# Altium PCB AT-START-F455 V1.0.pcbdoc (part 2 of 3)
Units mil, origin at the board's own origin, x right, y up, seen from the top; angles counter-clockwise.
Board outline 10945.53 x 3554 mil, 2 copper layers (Top Layer, Bottom Layer); 149 components, 197 nets, 740 pads, 768 vias.
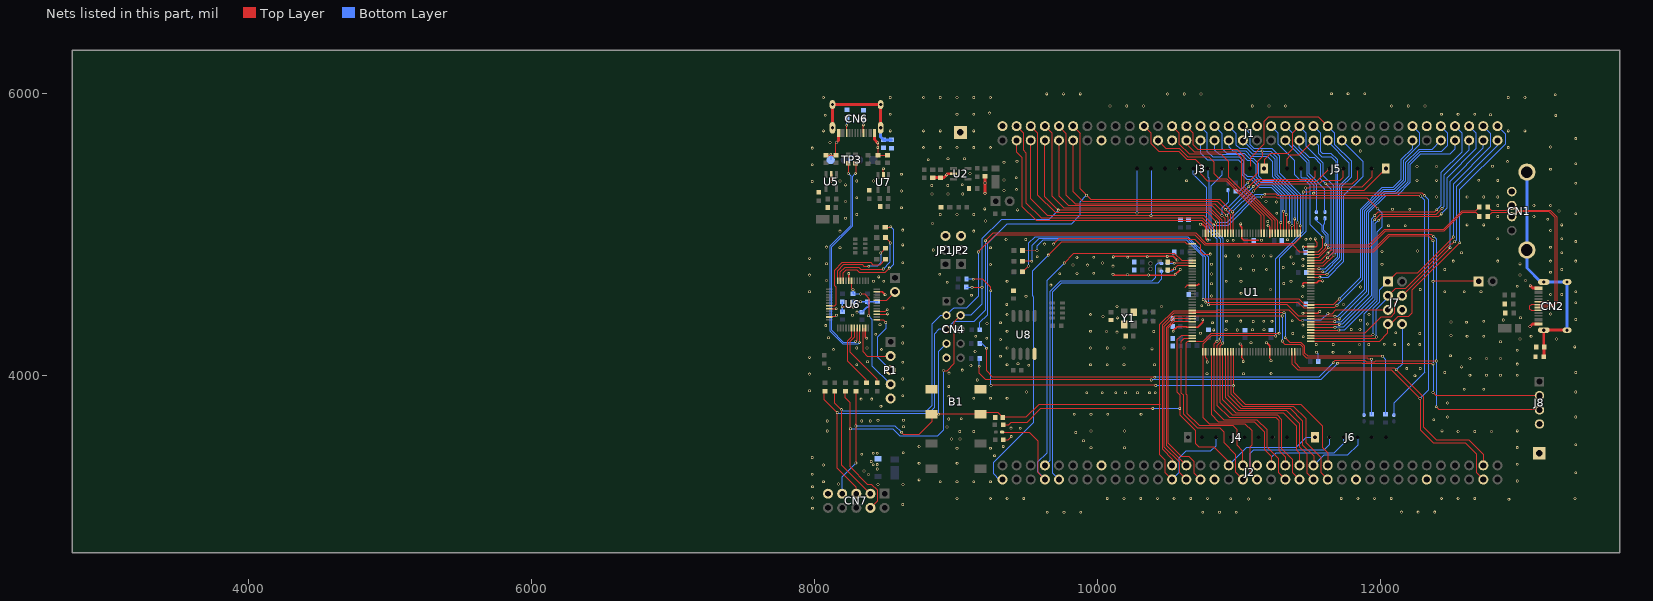
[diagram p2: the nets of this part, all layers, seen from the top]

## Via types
v1: diameter 19.7, hole 11.8, Top Layer to Bottom Layer, 425 vias
v2: diameter 19.68, hole 11.81, Top Layer to Bottom Layer, 331 vias
v3: diameter 31.5, hole 19.68, Top Layer to Bottom Layer, 10 vias
v4: diameter 27.56, hole 19.68, Top Layer to Bottom Layer, 2 vias

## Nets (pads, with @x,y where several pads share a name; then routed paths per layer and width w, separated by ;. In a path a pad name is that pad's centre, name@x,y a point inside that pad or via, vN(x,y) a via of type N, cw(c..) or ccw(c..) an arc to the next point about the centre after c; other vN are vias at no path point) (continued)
BOOT0: CN4.4 CN7.4 J1.66 R13.2 R45.2 U1.138 | length 5703.8
  Top Layer w6: R45.2@8218.66,3892.68 8218.66,3846.33 8253.97,3811.01 8253.97,3355.87 8378.26,3231.58 8403.96,3231.58 8446.06,3189.58 8446.06,3117.18 CN7.4@8395.46,3066.58 ; v2(8912.21,4037.97) 8937.81,4037.97 8987.5,4087.66 8987.5,4382.24 CN4.4@9033.23,4427.98 ; v2(9113.66,4626.6) v2(9184.53,4626.6) ; J1.66@9629.16,5665.18 9629.16,5266.98 v2(9724.26,5171.98) 10791.16,5171.98 10863.86,5099.28 U1.138@10863.86,5008.28
  Bottom Layer w6: v2(8254.21,3625.97) 8554.21,3625.97 8603.22,3576.97 8870.92,3576.97 8912.21,3618.25 v2(8912.21,4037.97) ; CN4.4@9033.26,4427.98 9105.76,4428.18 9183.26,4505.68 9183.26,4968.98 9319.14,5104.86 9657.14,5104.86 v2(9724.26,5171.98) ; R13.2@9071.76,4627.98 9073.06,4626.58 v2(9113.66,4626.6)
CC1: CN6.A5 R86.1 | length 101.4
  Top Layer w6: v1(8345.57,5774.61) 8346.41,5773.78 CN6.A5@8346.41,5717.9
  Bottom Layer w6: v1(8345.57,5774.61) R86.1@8345.57,5818.95
CC2: CN6.B5 R87.1 | length 106.2
  Top Layer w6: v1(8227.57,5772.61) 8228.31,5771.88 CN6.B5@8228.31,5717.9
  Bottom Layer w6: v1(8227.57,5772.61) 8227.57,5799.08 8229.57,5801.08 R87.1@8229.57,5822.95
EGND: C20.2 CN6.13 CN6.14 CN6.15 CN6.16 R88.1 | length 818.4
  Top Layer w20: CN6.14@8127.11,5753.9 CN6.16@8127.11,5918.5 CN6.15@8467.31,5918.5 CN6.13@8467.31,5753.9
  Bottom Layer w20: CN6.13@8467.31,5753.9 8467.31,5690.44 C20.2@8489.57,5668.17 8543.47,5668.17 R88.1@8543.57,5668.27
EGND1: C21.1 CN1.SH1 CN1.SH2 CN2.13 CN2.14 CN2.15 CN2.16 R35.2 | length 1697.7
  Top Layer w6: R35.2@13157.7,4135.42 R35.2@13159.6,4137.32
  Top Layer w20: C21.1@13156.94,4203.42 CN2.13@13156.94,4323.72 CN2.15@13321.54,4323.72 ; R35.2@13159.6,4137.32 C21.1@13159.6,4203.42
  Bottom Layer w20: CN1.SH1@13037.41,5440.9 CN1.SH2@13037.41,4889.71 13037.41,4761.79 13135.29,4663.92 CN2.14@13156.94,4663.92 CN2.16@13321.54,4663.92 CN2.15@13321.54,4323.72
GND: B1.2 B1.4 C1.1 C2.1 C3.1 C4.1 C5.2 C6.2 C7.2 C8.1 C9.1 C10.1 C11.1 C12.1 C13.2 C14.1 C15.1 C16.1 C17.1 C18.1 C19.1 C20.1 C21.2 C22.1 C23.2 C24.2 C25.2 C26.2 C27.2 C28.2 C29.2 C30.2 C31.2 C32.2 C33.2 C34.2 C35.2 C36.2 C37.2 C38.2 C39.2 C40.2 CN1.4 CN2.A1B12 CN2.B1A12 CN4.9 CN6.A1B12 CN6.B1A12 CN7.9 D4.2 J1.11 J1.22 J1.35 J1.48 J1.58 J1.71 J2.16 J2.31 J2.38 J2.51 J2.61 J3.7 J4.6 J4.7 J7.6 J8.4 JP1.3 JP2.3 LED1.2 P1.5 R15.2 R18.1 R32.1 R33.1 R35.1 R49.2 R51.2 R86.2 R87.2 R88.2 T1.1 T2.1 TP3.4 U1.16 U1.31 U1.38 U1.51 U1.61 U1.83 U1.94 U1.107 U1.120 U1.130 U1.143 U2.2 U5.2 U6.8 U6.20 U6.23 U6.35 U6.39 U6.40 U6.47 U7.2 U8.4 Y1.2 Y1.4 | length 5994.8
  Top Layer w5.98: v1(9689.57,4931.61) 9729.57,4971.61 10638.94,4971.61 10643.09,4967.46
  Top Layer w6: C18.1@8080.37,5561.37 8149.57,5561.37 C19.1@8150.37,5560.57 8150.37,5644.21 v2(8156.11,5649.96) ; U6.23@8104.58,4416.72 8142.48,4416.72 v2(8155.17,4429.41) ; U6.20@8104.58,4475.78 8153.2,4475.78 v2(8153.97,4475.01) ; v2(8196.37,4489.41) 8197.17,4488.61 8272.57,4488.61 v2(8273.57,4487.61) ; U6.39@8439.23,4436.41 8515.15,4436.41 v2(8516.94,4438.2) ; U6.40@8439.23,4456.09 8501.93,4456.09 v2(8514.03,4468.19) ; v2(8447.17,5647.41) v1(8447.17,5615.61) 8447.17,5584.75 8448.56,5583.36 C15.1@8448.56,5561.61 C16.1@8517.56,5561.61 ; v2(8487.17,5464.21) 8487.34,5464.05 U7.2@8487.34,5418.39 ; R18.1@9335.87,3547.97 9369.42,3547.97 v1(9391.96,3570.51) ; 10618.26,4623.08 10634.36,4639.18 ; 10643.09,4967.46 10689.19,4967.46 10729.37,4927.27 10729.37,4880.81 10749.38,4860.8 v1(10798.05,4860.8) ; U1.38@10765.46,4171.68 10765.46,4128.38 10776.57,4117.27 v1(10776.57,4097.61) ; U1.51@11021.36,4171.68 11021.36,4127.78 11031.5,4117.74 ; v1(11031.57,4102.61) 11031.57,4117.67 ; 11218.16,4134.08 11218.16,4127.28 11227.57,4117.87 v1(11227.57,4106.61) ; v1(11453.48,4442.3) U1.83@11508.48,4442.35 ; v1(11541.13,4968.64) 11541.13,4954.35 11551.32,4944.15 11551.32,4916.85 11549.26,4914.78
  Top Layer w10: U6.8@8242.36,4672.68 8242.43,4672.75 v2(8242.43,4723.22) ; U6.35@8360.49,4337.98 8360.49,4275.35 v2(8369.66,4266.18) ; U6.47@8439.26,4593.88 8478.39,4594.19 v2(8499.17,4573.41) ; v1(10110.79,4718.95) 10118.65,4711.1 10544.67,4711.1 v1(10585.67,4752.1) ; v1(10111.81,4841.3) 10115.31,4844.81 v1(10495.01,4844.81) 10538.1,4844.81 v1(10563.99,4818.91) ; v1@10538.26,4321.28 10565.16,4348.18 10628.39,4348.18 10632.7,4343.88 U1.31@10671.86,4343.93 10711.26,4343.88 10744.91,4377.54 v1(10744.91,4396.83) ; 10631.46,4639.18 10634.36,4639.18 U1.16@10671.86,4639.2 10708.16,4639.18 10721.56,4652.58 ; v1(10729.21,5072.19) 10743.36,5072.19 10765.36,5050.18 U1.143@10765.37,5008.31 10765.36,4968.98 v1@10772.76,4961.68 ; v1(11009.57,4225.61) 11021.26,4213.93 U1.51@11021.27,4171.68 11021.26,4129.48 ; v1@11011.86,5076.32 11011.86,5061.58 11021.36,5052.18 11021.36,5008.31 11021.36,4972.08 11034.26,4959.18 11143.06,4959.18 ; v1(11196.57,4233.61) 11218.16,4212.03 11218.16,4171.68 11218.16,4134.08 ; v1@11214.76,5056.08 11218.16,5052.78 11218.16,5008.31 11218.16,4975.38 ; v1(11453.53,4634.21) 11453.19,4634.55 11453.19,4651.81 11460.26,4658.88 U1.94@11508.48,4658.89 11553.16,4658.88 11565.89,4671.61 v2(11592.57,4671.61) ; v1(11456.57,4910.61) 11456.57,4914.78 U1.107@11508.48,4914.79 11549.26,4914.78 ; U1.83@11508.56,4442.28 11559.66,4442.28 v1(11572.76,4455.38)
  Top Layer w15: U5.2@8118.56,5424.05 8119.17,5423.44 v2(8119.17,5375.81)
  Top Layer w20: v2(8156.11,5649.96) 8170.41,5664.25 CN6.B1A12@8170.41,5717.9 ; CN6.A1B12@8424.21,5717.9 8424.21,5670.38 v2(8447.17,5647.41) ; C5.2@8836.21,5402.05 C6.2@8891.21,5402.05 8915.36,5402.08 v1(8934.33,5421.12) 8942.16,5428.98 U2.2@8984.26,5428.98 ; C7.2@9206.16,5410.48 v1(9206.16,5364.21) v1(9206.16,5291.98) v1@9206.26,5291.98 ; v1(13059.04,4349.42) 13076.44,4366.82 CN2.A1B12@13120.94,4366.82 ; v1(13061.04,4637.42) 13077.84,4620.62 CN2.B1A12@13120.94,4620.62
  Bottom Layer w5.98: v1(11549.18,4167.71) 11561.77,4155.12 C29.2@11561.77,4101.97
  Bottom Layer w6: TP3.4@8114.58,5526.61 v1(8114.57,5566.61) ; v2(8273.57,4487.61) 8273.97,4488.01 C22.1@8273.97,4524.65 ; v2(8300.41,4450.97) C11.1@8335.17,4450.97 ; v1(10781.23,4959.9) 10802.13,4959.9 10802.77,4959.26 ; v1(11456.57,4910.61) 11456.57,4889.17 C32.2@11473.13,4872.61
  Bottom Layer w10: C12.1@8196.37,4524.65 v2(8196.37,4489.41) 8196.77,4489.01 C10.1@8196.77,4453.77 ; C22.1@8273.97,4524.65 v2(8325.27,4524.65) C9.1@8376.37,4524.65 ; C11.1@8335.17,4450.97 8371.21,4487.01 8375.17,4487.01 8382.24,4494.09 8382.24,4504.09 8376.37,4509.96 C9.1@8376.37,4524.65 ; C9.1@8376.37,4525.05 C9.1@8376.37,4524.65 ; C8.1@8446.37,4525.85 8418.65,4525.85 8417.45,4524.65 C9.1@8376.37,4524.65
  other v1: 9646.44,3035.82 9764.55,3035.82 9882.66,3035.82 10745.74,3035.82 10863.85,3035.82 10981.96,3035.82 12150.21,3036.6 12268.32,3036.6 12386.43,3036.6 7986.57,3063.61 8624.57,3090.61 12910.14,3128.29 11068.29,3129.68 10942.92,3130.71 11218.56,3130.71 9007.66,3133.82 9243.88,3133.82 9361.99,3133.82 9480.1,3133.82 10070.65,3133.82 10188.76,3133.82 10306.87,3133.82 10424.98,3133.82 10543.09,3133.82 10661.2,3133.82 10779.31,3133.82 11724.2,3133.82 11842.31,3133.82 11960.42,3133.82 12078.53,3133.82 12432.86,3133.82 12550.97,3133.82 12669.08,3133.82 13377.74,3133.82 7986.57,3136.61 7986.57,3216.61 8449.57,3231.61 8625.57,3231.61 8169.57,3235.61 8062.78,3251.94 8889.55,3251.94 9007.66,3251.94 9125.77,3251.94 9243.88,3251.94 8739.57,3264.39 8382.07,3302.11 7984.57,3304.39 8350.57,3327.61 8443.57,3341.61 8062.78,3370.05 8415.07,3372.14 8443.57,3372.61 9008.57,3381.61 8739.57,3382.5 8402,3394.41 7984.57,3422.5 9273.57,3434.61 8333.57,3445.61 8415.57,3452.61 8443.57,3452.61 8627.57,3456.61 9007.66,3488.16 9243.88,3488.16 9955.57,3491.61 10191.55,3492.51 8739.57,3500.61 9334.55,3501.51 9902.57,3541.61 8968.57,3553.61 9028.57,3553.61 9847.57,3599.61 9027.66,3606.27 9125.77,3606.27 12550.97,3606.27 12669.08,3606.27 12787.19,3606.27 8089.57,3610.61 9955.33,3610.62 10191.55,3610.62 9455.57,3629.61 9389.57,3630.61 8936.59,3638.67 8629.57,3640.61 8089.57,3680.61 8334.57,3680.61 8394.57,3680.61 8449.57,3685.61 8629.57,3685.61 8949.57,3695.61 9037.57,3696.61 9837.22,3728.73 9955.33,3728.73 10073.44,3728.73 10309.66,3728.73 8469.57,3785.61 8329.57,3835.61 8404.57,3835.61 9125.77,3842.49 9243.88,3842.49 9361.99,3842.49 8949.57,3855.61 8624.57,3859.39 9924.57,3880.61 10034.57,3880.61 10129.57,3880.61 10199.57,3880.61 10284.57,3880.61 10369.57,3880.61 10409.57,3880.61 9499.57,3885.61 7964.57,3894.39 8949.57,3925.61 9150.77,3970.6 8624.57,3977.5 7964.57,4012.5 10775.57,4015.31 11033.65,4015.54 11228.8,4015.85 8951.08,4019.38 9044.57,4040.61 12187.22,4051.45 8104.57,4052.5 9105.77,4073.71 9514.57,4075.61 8299,4078.71 9361.99,4078.71 9952.54,4078.71 10070.65,4078.71 10188.76,4078.71 10404.57,4079.39 9439.57,4085.61 8624.57,4095.61 8374.57,4100.61 7964.57,4130.61 9314.57,4139.39 11667.29,4167.71 11785.4,4167.71 9135.77,4171.82 8134.57,4185.61 8474.57,4185.61 10386.94,4190.74 8299,4196.82 8371.4,4197.15 9361.99,4196.82 9952.54,4196.82 10070.65,4196.82 10188.76,4196.82 13376.17,4204.95 11547.64,4221.77 11668.11,4222.05 11853.37,4222.42 11919.21,4221.67 12029.3,4223.51 8624.57,4232.5 11086.46,4234.02 9314.57,4257.5 13247.06,4261 9218.34,4266.61 8099.57,4269.39 11456.18,4277.39 9139.57,4280.61 12500.3,4285.22 8432.74,4294.95 11381.5,4299.17 10730.04,4301.05 12110.21,4304.89 10139.64,4309.43 10064.81,4313.39 10399.24,4313.56 9361.99,4314.93 9952.54,4314.93 10536.27,4315.64 10988.84,4324.34 10823.72,4325.3 11178.64,4325.5 10909.7,4325.83 11096.88,4325.83 11796.21,4328.23 11856.41,4327.54 8624.57,4350.61 8079.57,4355.61 11453.44,4358.89 8463.33,4361.23 11911.3,4366.97 9219.57,4370.61 9314.57,4375.61 10813.35,4375.83 12609.62,4379.62 12500.6,4380.55 11102.16,4385 10914.13,4386.53 11013.73,4387.03 11176.75,4386.64 11234.34,4386.64 11378.97,4389.82 11860.56,4393.27 10141.94,4409.99 10040.24,4419.68 8269,4428.04 9361.99,4433.04 9952.54,4433.04 11921.44,4433.4 8625.22,4479.93 10454.31,4490.33 10138.63,4491.28 10738.1,4495.53 11740.53,4504.27 9359.57,4505.61 11451.68,4561.79 9495.17,4563.45 10808.14,4564.69 9109.57,4570.61 11016.87,4583.72 7964.57,4594.39 11224.09,4610.88 11861.61,4628.12 9671.57,4641.61 10807.75,4650.9 11318.07,4653.66 8938.27,4661.7 8417.11,4669.26 9361.99,4669.26 10910.91,4669.26 11015.53,4669.26 11369.87,4669.26 8489.51,4669.59 8084.57,4674.39 8454.25,4700 7964.57,4712.5 10361.2,4713.59 10212.96,4717.08 10551.25,4717.89 8886.25,4718.87 10807.6,4720.14 9734.57,4722.61 9855.76,4724.84 9973.91,4725.6 11104.74,4746.83 11197.11,4751.82 11013.41,4757.21 11315.3,4766.21 10110.53,4776.01 11453.53,4779.43 9930.71,4783.37 9827.67,4784.29 9243.88,4787.37 10807.5,4788.89 12012.44,4789.56 8084.57,4792.5 11387.57,4795.61 10036.4,4797.96 8624.57,4799.39 11453.53,4824.94 7964.57,4830.61 9855.25,4837.91 9974.68,4839.18 11370.06,4841.01 10352.6,4841.64 9575.57,4842.61 11000.57,4847.61 11097.57,4847.61 11174.57,4847.61 10907.57,4848.61 11227.57,4848.61 12012.54,4880.38 12263.98,4882.46 8839.57,4890.61 8180.89,4905.48 9243.88,4905.48 8084.57,4910.61 8624.57,4926.25 9626.57,4931.61 10919.94,4958 10961.57,4958.61 11160.57,4959.61 11345.57,4962.61 9355.15,4964.33 9493.64,4964.29 11474.74,4966.62 11507.95,4967.22 8180.89,5023.59 9125.77,5023.59 8624.26,5030.62 12059.64,5060.92 12178.03,5061.23 11207.57,5062.61 11013.57,5074.61 8834.96,5078.07 11205.57,5091.61 9209.57,5095.61 8219.57,5114.39 8299,5141.7 8889.55,5141.7 9007.66,5141.7 9125.77,5141.7 9435.18,5173.68 12087.17,5178.39 12209.79,5177.93 9204.57,5180.61 8614.57,5189.39 8219.57,5232.5 8299,5259.81 8831.46,5285.61 8944.57,5285.61 9047.68,5285.61 8614.57,5307.5 9339.57,5310.61 9428.04,5317.21 8829.57,5345.61 8942.68,5345.61 8219.57,5350.61 9045.17,5351.15 7984.57,5374.39 8180.89,5377.92 8299,5377.92 8417.11,5377.92 10631.33,5379.73 12696.74,5383.89 9339.57,5384.93 9427.35,5400.89 8614.57,5425.61 9099.57,5430.61 12793.91,5482.06 7984.57,5492.5 9339.57,5510.61 12900.76,5515.24 9431.5,5517.07 8804.71,5527.77 9060.59,5535.15 8944.57,5535.61 11859.02,5590.1 7984.57,5610.61 8771.44,5614.14 8889.55,5614.14 9007.66,5614.14 9125.77,5614.14 9243.88,5614.14 12905.3,5614.14 8109.57,5650.61 8062.78,5732.25 8535.22,5732.25 8771.44,5732.25 8889.55,5732.25 9125.77,5732.25 12905.3,5732.25 13023.41,5732.25 13240.91,5841.93 8076.21,5843.18 12780.53,5846.89 8535.22,5850.36 9007.66,5850.36 9125.77,5850.36 12432.86,5850.36 12550.97,5850.36 12669.08,5850.36 9237.66,5857.97 11095.21,5908.35 11213.32,5908.35 11331.43,5908.35 12080.8,5908.48 12198.91,5908.48 12317.02,5908.48 10089.92,5908.57 10208.03,5908.57 10326.14,5908.57 8062.78,5968.47 8535.22,5968.47 8771.44,5968.47 8889.55,5968.47 9007.66,5968.47 9125.77,5968.47 9243.88,5968.47 12905.3,5968.47 13023.41,5968.47 13237.8,5987.23 10497.05,5992.74 10615.16,5992.74 10733.27,5992.74 9642.7,5994.01 9760.81,5994.01 9878.92,5994.01 11655.09,5994.49 11773.2,5994.49 11891.31,5994.49
  other v2: 12968.94,3256.52 13382.33,3315.58 12968.94,3374.63 12968.94,3492.74 13382.33,3512.43 12437.44,3610.85 12968.94,3610.85 12378.39,3689.59 12476.81,3709.28 13382.33,3709.28 12476.81,3807.7 13382.33,3886.44 12594.92,3906.13 12732.72,3906.13 12245.65,4001.58 12634.29,4004.55 12752.4,4004.55 12850.83,4004.55 12968.94,4004.55 12457.13,4024.24 13382.33,4024.24 12283.52,4052.08 12575.24,4063.61 12968.94,4083.29 12634.29,4122.66 12752.4,4122.66 12850.83,4122.66 12496.5,4142.35 12968.94,4181.72 12102.8,4221.09 12201.22,4221.09 12279.96,4221.09 12850.83,4240.77 12988.62,4260.46 12614.61,4280.14 12732.72,4280.14 13067.36,4280.14 12279.96,4299.83 12733.17,4386.53 12870.02,4395.19 13382.33,4398.25 12992.44,4411.43 13205.16,4437.62 13264.22,4476.99 13382.33,4516.36 13205.16,4575.42 13283.9,4575.42 12457.13,4595.1 12594.92,4595.1 12713.03,4595.1 13382.33,4595.1 12283.31,4610.65 12968.94,4634.47 13027.99,4673.84 12988.62,4713.21 13205.16,4732.9 12457.13,4752.58 13283.9,4752.58 12988.62,4791.95 12516.18,4811.64 12831.14,4811.64 13205.16,4811.64 13382.33,4811.64 10214.62,4838.9 12575.24,4870.69 13283.9,4870.69 13205.16,4910.06 13382.33,4949.43 12831.14,4969.12 13283.9,4969.12 13205.16,5028.17 12614.61,5067.54 12732.72,5067.54 13283.9,5067.54 13185.48,5106.91 12831.14,5126.6 13087.05,5126.6 13382.33,5146.28 11269.02,5149.4 13264.22,5165.97 12831.14,5205.34 13087.05,5205.34 13205.16,5205.34 11267.52,5229.07 11192.66,5232.67 12398.07,5264.39 12614.61,5264.39 12732.72,5264.39 12831.14,5264.39 13382.33,5362.82 12260.28,5382.5 12398.07,5382.5 12831.14,5382.5 13205.16,5461.24 12260.28,5480.93 12398.07,5480.93 13382.33,5500.61 13205.16,5618.73 13382.33,5677.78
LD1: LD1.2 U6.10 | length 760.9
  Top Layer w6: U6.10@8203.01,4672.63 8203.01,4728.05 8223.97,4749.01 8299.93,4749.01 8315.93,4733.01 8499.57,4733.01 v2(8528.37,4761.81) ; LD1.2@8500.43,5052.63 8537.59,5052.63 v2(8538.77,5053.81)
  Bottom Layer w6: v2(8528.37,4761.81) 8530.37,4761.81 8558.77,4790.21 8558.77,5033.81 v2(8538.77,5053.81)
LD2: LD2.2 U6.11 | length 643.9
  Top Layer w6: U6.11@8183.32,4672.63 8183.32,4735.97 8216.77,4769.41 8312.03,4769.41 8326.03,4755.41 v2(8485.57,4755.41) ; LD2.2@8501.39,4978.53 8536.37,4943.56 v2(8536.37,4939.81)
  Bottom Layer w6: v2(8485.57,4755.41) 8536.37,4806.21 v2(8536.37,4939.81)
LD3: LD3.2 U6.12 | length 524.6
  Top Layer w6: U6.12@8163.64,4672.63 8163.64,4744.28 8207.17,4787.81 8337.17,4787.81 8349.13,4775.86 v2(8382.95,4775.86) ; v2(8467.97,4868.61) 8468.42,4868.61 LD3.2@8501.43,4901.63
  Bottom Layer w6: v2(8382.95,4775.86) 8443.61,4775.86 8467.97,4800.21 v2(8467.97,4868.61)
LD4: LD4.2 U6.19 | length 706.4
  Top Layer w6: U6.19@8104.58,4495.46 8143.22,4495.46 8153.17,4505.41 8153.17,4626.61 8141.57,4638.21 8141.57,4748.21 8196.77,4803.41 8397.57,4803.41 8413.57,4787.41 8464.77,4787.41 8501.39,4824.04 LD4.2@8501.39,4825.63
M-ATLK_RX: R48.1 U6.31 | length 483.9
  Top Layer w6: U6.31@8281.76,4337.98 8281.76,4271.98 8249.46,4239.58 8249.46,4170.28 8440.46,3979.28 R48.1@8440.46,3946.58
M-ATLK_TX: R47.1 U6.30 | length 457.3
  Top Layer w6: U6.30@8262.06,4337.98 8262.06,4276.28 8234.66,4248.88 8234.66,4102.88 8366.46,3971.08 R47.1@8366.46,3946.58
M-BOOT0: J9.2 U6.44 | length 154.6
  Top Layer w6: U6.44@8439.26,4534.88 8510.66,4534.88 J9.2@8569.46,4593.68
M-NRST: C22.2 P1.4 U6.7 | length 893.3
  Top Layer w6: U6.7@8262.06,4672.68 8262.06,4619.48 v2(8272.16,4609.38) ; v2(8324.77,4579.01) 8353.97,4579.01 8382.37,4550.61 v2(8382.37,4424.61)
  Bottom Layer w6: C22.2@8273.97,4579.77 8324.01,4579.77 v2(8324.77,4579.01) ; v2(8382.37,4424.61) 8409.57,4397.41 8409.57,4068.77 P1.4@8538.16,3940.18
  Bottom Layer w10: v2(8272.16,4609.38) 8273.97,4607.57 C22.2@8273.97,4579.77
M-SWCLK: P1.3 U6.37 | length 475.2
  Top Layer w6: U6.37@8439.26,4397.04 8484.75,4397.04 v2(8504.37,4377.41)
  Bottom Layer w6: v2(8504.37,4377.41) 8504.37,4333.01 8443.17,4271.81 8443.17,4135.17 P1.3@8538.16,4040.18
M-SWDIO: P1.2 U6.34 | length 376.2
  Top Layer w6: U6.34@8340.8,4337.98 8340.76,4172.56 8373.14,4140.18 P1.2@8538.16,4140.18
M-USB_DM: R12.2 U6.32 | length 1557.9
  Top Layer w6: v2(8289.29,5431.83) 8290.08,5432.61 R12.2@8290.08,5505.16 ; v2(8290.51,4244.08) 8301.46,4255.04 U6.32@8301.46,4337.98
  Bottom Layer w6: v2(8289.29,5431.83) 8270.37,5412.9 8270.37,5061.25 8122.77,4913.65 8122.77,4321.44 8208.23,4235.98 8282.42,4235.98 v2(8290.51,4244.08)
M-USB_DP: R11.2 U6.33 | length 1610.2
  Top Layer w6: R11.2@8238.07,5504.37 8238.07,5432.9 v2(8239.61,5431.36) ; v2(8317.31,4236.99) 8321.16,4240.86 U6.33@8321.16,4337.98
  Bottom Layer w6: v2(8239.61,5431.36) 8258.37,5412.6 8258.37,5066.22 8110.77,4918.62 8110.77,4316.47 8203.26,4223.98 8304.31,4223.98 v2(8317.31,4236.99)
NRST: B1.1 B1.3 C40.1 CN4.7 CN7.7 J2.25 J4.3 J7.5 R46.2 U1.25 | length 7009.8
  Top Layer w6: v2(8292.66,3383.78) 8292.81,3383.93 8292.81,3663.13 8292.66,3662.98 ; v1(8292.66,3645.23) 8292.66,3662.98 ; R46.2@8292.66,3892.68 8292.66,3662.98 ; v2(8616.21,3600.97) 8632.56,3584.61 8738.57,3584.61 8828.03,3674.07 B1.3@8828.03,3728.39 B1.1@9174.49,3728.39 9185.06,3738.98 9298.26,3738.98 C40.1@9331.77,3705.97 9495.26,3705.98 9584.26,3794.98 10439.66,3794.98 10439.66,3796.08 10441.57,3797.96 ; J2.25@10529.17,3267.08 10480.26,3316.08 10480.26,3403.93 10441.57,3442.61 10441.57,3797.96 ; v2(11451.16,4391.98) 11428.2,4391.98 11354.2,4465.98 10846.66,4465.98 10842.76,4461.98 U1.25@10671.86,4462.04 10539.66,4461.98 10441.57,4363.89 10441.57,3797.96 ; v2(11630.21,4440.97) 11659.92,4440.97 11685.51,4466.56 J7.5@12054.81,4466.56
  Bottom Layer w6: CN7.7@8195.43,3166.63 8195.43,3286.55 v2(8292.66,3383.78) ; v1(8292.66,3645.23) 8571.94,3645.23 v2(8616.21,3600.97) ; v2(8879.21,3727.97) 8879.21,4173.95 CN4.7@8933.23,4227.98 ; J2.25@10529.17,3267.08 10579.26,3317.08 10579.26,3420.98 10627.26,3468.98 10803.36,3468.98 10839.86,3505.48 J4.3@10839.86,3565.98 ; v2(11451.16,4391.98) 11581.22,4391.98 v2(11630.21,4440.97)
OTGFS1_D+: CN1.3 CN2.A6 CN2.B6 R30.2 | length 1405.1
  Top Layer w5.98: R30.2@12760.64,5194.62 12785.25,5170.01 12896.06,5170.01 CN1.3@12930.72,5204.67 ; CN2.B6@13120.94,4523.32 13122.01,4523.32 13122.78,4524.08 13184.72,4524.08 v2(13186.21,4525.57)
  Top Layer w6: CN1.3@12930.72,5204.67 12939.2,5204.67 12972.24,5171.63 13200.9,5171.63 13248.97,5123.56 13248.97,4515.74 13216.94,4483.71 v2(13189.49,4483.71) 13121.24,4483.71 CN2.A6@13120.94,4484.02
  Bottom Layer w5.98: v2(13186.21,4525.57) 13189.49,4522.28 v2(13189.49,4483.71)
OTGFS1_D-: CN1.2 CN2.A7 CN2.B7 R31.2 | length 1410.6
  Top Layer w5.98: R31.2@12760.64,5127.69 12760.64,5127.82 12790.87,5158.04 12898.6,5158.04 CN1.2@12930.72,5125.93 ; CN2.B7@13120.94,4464.32 13067.48,4464.32 13055.8,4475.99 13055.8,4492.81 13066.61,4503.62 CN2.A7@13120.94,4503.62
  Top Layer w6: CN1.2@12930.72,5125.93 12939.2,5125.93 12972.9,5159.63 13195.93,5159.63 13236.97,5118.59 13236.97,4520.71 13220.43,4504.17 13121.49,4504.17 CN2.A7@13120.94,4503.62
PA0: J2.34 J6.1 R19.2 U1.34 | length 3215.2
  Top Layer w6: R19.2@9332.66,3653.98 9372.02,3653.98 9391.72,3673.68 9504.96,3673.68 9601.26,3769.98 v2(10391.16,3769.98) ; U1.34@10671.86,4284.87 10592.84,4284.88 10562.26,4254.23 10562.26,3886.38 10583.26,3865.38 10583.26,3769.97 10583.26,3725.98 10692.26,3616.98 10692.26,3523.98 10717.26,3498.98 10823.26,3498.98 10929.16,3392.98 J2.34@10929.17,3367.08
  Bottom Layer w6: v2(10391.16,3769.98) v2(10583.21,3769.97) ; J2.34@10929.17,3367.08 11058.16,3495.98 11406.26,3495.98 11476.26,3565.98 J6.1@11539.86,3565.98
PA1: J2.35 J6.2 U1.35 | length 2180.2
  Top Layer w6: U1.35@10671.86,4265.19 10613.76,4265.18 10594.63,4246.05 10594.63,3878.41 10611.56,3861.48 10611.56,3728.68 10709.66,3630.58 10867.66,3630.58 10896.26,3601.98 10896.26,3525.98 10978.26,3443.98 10978.26,3318.08 J2.35@11029.17,3267.08
  Bottom Layer w6: J2.35@11029.17,3267.08 11078.26,3315.98 11078.26,3449.98 11102.26,3473.98 11600.16,3473.98 11639.86,3513.58 J6.2@11639.86,3565.98
PA2: J2.36 J5.2 U1.36 | length 3526.8
  Top Layer w6: J2.36@11029.17,3367.08 11029.16,3466.98 10988.26,3507.98 10988.26,3619.98 10962.26,3645.98 10723.16,3645.98 10637.36,3731.78 10637.36,3862.08 10628.51,3870.93 10628.51,4233.83 10640.16,4245.48 U1.36@10671.86,4245.5 10748.11,4245.48 10804.61,4301.98 v2(11285.21,4301.97) ; v2(11472.46,5327.97) 11493.46,5327.97 11499.37,5333.88 11870.76,5333.88 11939.76,5402.88 J5.2@11939.8,5465.97
  Bottom Layer w6: v2(11285.21,4301.97) 11285.21,4830.64 11474.03,5019.47 11474.03,5279.85 11477.58,5283.4 11477.58,5308.44 11474.03,5311.99 11474.03,5326.4 v2(11472.46,5327.97)
PA3: J2.37 J5.1 U1.37 | length 3567.5
  Top Layer w6: J2.37@11129.17,3267.08 11078.26,3318.08 11078.26,3493.98 11092.26,3507.98 11092.26,3613.88 11043.96,3662.18 10789.96,3662.18 10745.76,3706.38 10745.76,4171.68 10745.76,4222.64 10805.1,4281.98 v2(11262.21,4281.97) ; v2@11455.95,5300.35 11497.63,5300.35 11510.26,5312.98 11886.86,5312.98 J5.1@12039.8,5465.97
  Bottom Layer w6: v2(11262.21,4281.97) 11262.21,4829.25 11456.7,5023.74 11456.7,5299.6 v2(11455.91,5300.39)
PA4: J2.40 J6.3 U1.40 | length 1779.9
  Top Layer w6: U1.40@10804.76,4171.68 10804.76,3728.38 10856.46,3676.68 11108.56,3676.68 11180.26,3604.98 11180.26,3481.18 11229.16,3432.28 J2.40@11229.17,3367.08
  Bottom Layer w6: J2.40@11229.17,3367.08 11229.16,3422.98 11260.26,3453.98 11672.26,3453.98 11739.86,3521.58 J6.3@11739.86,3565.98
PA5: J2.41 J3.6 U1.41 | length 2624.8
  Top Layer w6: v2(10845.74,4244.57) 10845.74,4243.88 10824.46,4222.6 10824.46,4171.68 10824.46,3761.68 10895.26,3690.98 11128.16,3690.98 11196.26,3622.98 11196.26,3497.98 11278.26,3415.98 11278.26,3318.08 J2.41@11329.17,3267.08
  Bottom Layer w6: J3.6@10679.86,5465.98 10679.86,5424.38 10772.26,5331.98 10772.26,5041.78 10849.23,4964.8 10849.23,4248.06 v2(10845.74,4244.57)
PA6: J2.42 J3.5 U1.42 | length 2540.2
  Top Layer w6: v2(10868.07,4261.17) 10868.07,4238.25 10844.16,4214.33 10844.16,4171.68 10844.16,3792.98 10931.26,3705.98 11262.26,3705.98 11282.26,3685.98 11282.26,3474.88 11329.16,3427.98 J2.42@11329.17,3367.08
  Bottom Layer w6: J3.5@10779.86,5465.98 10779.86,5409.38 10787.26,5401.98 10787.26,5049.37 10868.07,4968.55 v2(10868.07,4261.17)
PA7: J2.43 J3.4 U1.43 | length 2695.5
  Top Layer w6: v2(10886.92,4232.13) 10886.38,4232.13 10863.86,4209.61 10863.86,4171.68 10863.86,3814.88 10954.76,3723.98 11271.26,3723.98 11300.26,3694.98 11300.26,3489.98 11378.26,3411.98 11378.26,3318.08 J2.43@11429.17,3267.08
  Bottom Layer w6: J3.4@10879.86,5465.98 10879.86,5419.38 10802.26,5341.78 10802.26,5057.48 10886.92,4972.82 v2(10886.92,4232.13)
PA8: J1.28 J5.8 U1.100 | length 1430.8
  Top Layer w6: J5.8@11339.8,5465.97 11339.76,5533.38 11365.66,5559.28 11422.76,5559.28 J1.28@11529.16,5665.68 ; U1.100@11508.56,4776.98 11598.72,4776.98 11673.79,4852.05 v2(11673.79,4854.78)
  Bottom Layer w6: J1.28@11529.16,5665.68 11562.68,5632.15 11562.68,5573.01 11585.76,5549.98 11654.26,5549.98 11684.86,5519.38 11684.86,4865.84 v2(11673.79,4854.78)
PA9: J1.29 J3.1 J8.2 JP4.1 R25.2 U1.101 | length 8020.7
  Top Layer w5.98: v2(12373.57,3882.61) 12396.48,3859.71 J8.2@13126.44,3859.71 ; v2(12373.68,4669) 12374.07,4668.62 JP4.1@12695.57,4668.61
  Top Layer w6: v2@9165.26,4067.98 9165.26,4017.48 9211.76,3970.98 v2(10381.21,3970.97) ; J3.1@11179.86,5465.98 11179.86,5529.58 11222.26,5571.98 11346.26,5571.98 11378.26,5603.98 11378.26,5714.68 J1.29@11429.16,5765.68 ; U1.101@11508.56,4796.68 11588.96,4796.68 11628.26,4835.98 11667.76,4875.48 11952.56,4875.48 12063.39,4986.31 12342.77,4986.31 v2(12374.01,4955.07) ; v2(11699.01,4089.24) 11872.5,4089.2 11877.08,4084.61 v2(12373.57,4084.61)
  Bottom Layer w5.98: v2(12373.57,3882.61) v2(12373.57,4084.61) ; v2@12373.57,4668.89 v2(12373.68,4669)
  Bottom Layer w6: R25.2@9165.16,4123.08 9165.16,4068.18 v2@9165.26,4067.98 ; v2(10381.21,3970.97) 11580.74,3970.97 v2(11699.01,4089.24) ; J1.29@11429.16,5765.68 11478.26,5716.58 11478.26,5624.38 11598.26,5504.38 11598.26,5416.88 11670.26,5344.88 11670.26,4877.98 v2@11628.26,4835.98 ; v2(12373.57,4084.61) 12373.57,4668.89 12373.57,4954.63 v2(12374.01,4955.07)
  other v2: 9165.21,4067.97 11628.21,4835.97
PA10: J1.30 J5.3 J8.3 R24.2 U1.102 | length 7613.9
  Top Layer w5.98: v2(12396.57,3781.61) 12418.48,3759.71 J8.3@13126.44,3759.71
  Top Layer w6: v2(9217.21,4194.97) 9217.21,4034.97 9261.21,3990.97 v2(10406.21,3990.97) ; U1.102@11508.56,4816.38 11578.56,4816.38 v2(11630.21,4867.97) ; v2(11614.7,5358.7) 11803.86,5358.68 11839.76,5394.68 J5.3@11839.8,5465.97 ; v2@11630.26,4867.98 11649.76,4887.48 11947.59,4887.48 12058.33,4998.31 12365.28,4998.31 v2(12377.76,4985.83) ; v2(11667.45,4092.7) 11683.69,4108.94 11890.38,4108.94 11900.23,4099.09 11963.35,4099.09 11970.04,4105.78 v1(12396.06,4105.78)
  Bottom Layer w5.98: v2(12377.76,4985.83) 12395.57,4968.02 12395.57,4106.27 v1(12396.06,4105.78) 12396.06,3782.12 v2(12396.57,3781.61)
  Bottom Layer w6: R24.2@9165.76,4229.98 9182.16,4229.98 v2@9217.26,4194.98 ; v2(10406.21,3990.97) 11565.72,3990.97 v2(11667.45,4092.7) ; J1.30@11429.16,5665.68 11429.16,5612.78 11501.26,5540.78 11537.86,5540.78 11581.56,5496.98 11581.56,5391.78 v2(11614.7,5358.7) ; v2(11614.7,5358.7) 11655.27,5318.12 11655.27,5146.73 11655.27,4893.04 v2(11630.21,4867.97)
PA11: R31.1 R54.2 U1.103 | length 1571.4
  Top Layer w6: U1.103@11508.56,4835.98 11563.59,4835.98 11632.77,4905.16 v2(11632.82,4906) ; v2(11632.82,4906) 11652.43,4906 11659.92,4913.48 11926.02,4913.48 12037.82,5025.38 12454.67,5025.38 12585.35,5156.06 12674.09,5156.06 12701.32,5128.82 R31.1@12701.32,5127.69
  Bottom Layer w6: R54.2@11609.4,5114.26 11609.4,5078 11600.9,5069.51 11600.9,5028.93 11632.87,4996.96 v2@11632.87,4906.01 ; v2@11632.26,4913.98 11632.77,4913.47 v2(11632.82,4906)
PA11_E: J1.31 R54.1 | length 726
  Bottom Layer w6: J1.31@11329.16,5765.68 11380.26,5714.58 11380.26,5633.98 11497.66,5516.58 11497.66,5429.28 11608.26,5318.68 R54.1@11608.26,5155.28
PA12: R30.1 R55.2 U1.104 | length 1569.5
  Top Layer w6: U1.104@11508.56,4855.68 11566.31,4855.68 11613.36,4902.73 v2@11613.36,4926.2 ; v2(11612.72,4926.88) v2@11613.36,4926.2 ; R30.1@12701.32,5194.62 12701.32,5193.49 12675.88,5168.04 12580.39,5168.04 12450.4,5038.06 12033.53,5038.06 11920.95,4925.48 11614.08,4925.48 v2@11613.36,4926.2
  Bottom Layer w6: R55.2@11549.03,5099.37 R55.2@11549.03,5100.5 ; R55.2@11549.03,5113.47 R55.2@11549.03,5100.5 ; v2(11612.72,4926.88) 11612.67,4937.47 11620.26,4945.05 11620.26,4992.6 11588.9,5023.96 11588.9,5060.63 R55.2@11549.03,5100.5
PA12_E: J1.32 R55.1 | length 601.9
  Bottom Layer w6: J1.32@11329.16,5665.68 11329.16,5660.98 11483.06,5507.08 11483.06,5418.98 11550.16,5351.88 R55.1@11550.16,5155.28
PA13/SWDIO: CN4.3 CN7.3 J1.33 R44.2 U1.105 | length 6357.5
  Top Layer w6: R44.2@8144.46,3888.68 8144.46,3807.38 v2(8190.46,3761.38) 8190.46,3371.66 CN7.3@8395.46,3166.58 ; v2@9158.26,4875.98 9277.17,4994.9 10692.84,4994.9 10764.76,4922.98 11385.27,4922.98 11432.77,4875.38 U1.105@11508.48,4875.42 11559.66,4875.38 11590.86,4906.58 v2@11590.86,4980.18
  Bottom Layer w6: v2(8190.46,3761.38) 8199.22,3752.61 8793.57,3752.61 8832.26,3791.3 8832.26,4368.88 8891.53,4428.15 CN4.3@8933.23,4427.98 ; CN4.3@8933.26,4427.98 8970.96,4466.28 8983.16,4477.68 9072.16,4477.68 9158.26,4563.78 v2@9158.26,4875.98 ; J1.33@11229.16,5765.68 11280.26,5714.58 11280.26,5639.18 11397.56,5521.88 11397.56,5422.18 11436.26,5383.48 11470.86,5383.48 11506.76,5347.68 11506.76,5067.48 11590.86,4983.38 v2@11590.86,4980.18
  other v2: 9158.21,4875.97 11590.82,4980.14
PA14/SWCLK: CN4.5 CN7.5 J1.37 R41.2 U1.109 | length 6292.3
  Top Layer w6: R41.2@8070.46,3888.68 8070.46,3830.78 v2(8160.56,3740.58) 8161.97,3739.27 8161.97,3346.21 8295.46,3212.73 CN7.5@8295.46,3166.58 ; v2@9208.26,4955.98 9259.16,5006.88 10699.46,5006.88 10771.36,4934.98 11393.48,4934.98 11434.66,4976.15 U1.109@11434.66,5008.31 11435.16,5008.78 v2(11435.21,5061.97)
  Bottom Layer w6: v2(8160.56,3740.58) 8168.52,3732.61 8801.57,3732.61 8845.26,3776.3 8845.26,4294.08 8879.26,4328.18 ; 8880.73,4327.97 CN4.5@8933.23,4327.98 8933.23,4330.45 8984.76,4381.98 9126.96,4381.98 9208.26,4463.28 v2@9208.26,4955.98 ; J1.37@11029.16,5765.68 11078.26,5716.58 11078.26,5637.88 11106.16,5609.98 11234.26,5609.98 11286.26,5557.98 11286.26,5434.58 11435.16,5285.68 v2(11435.21,5061.97)
  other v2: 9208.21,4955.97
PA15: J1.38 R61.1 U1.110 | length 1263.8
  Top Layer w6: v2(11063.88,5365.01) 11130.86,5431.98 11130.86,5515.88 11164.96,5550.08 v2(11165,5589.98) ; U1.110@11414.97,5008.31 11415.16,5008.48 v2(11415.21,5083.97)
  Bottom Layer w6: R61.1@10979.26,5307.48 11006.36,5307.48 v2(11063.88,5365.01) ; J1.38@11029.16,5665.68 11104.86,5589.98 v2(11165,5589.98) ; v2(11165,5589.98) 11226.26,5589.98 11270.26,5545.98 11270.26,5426.18 11415.16,5281.28 v2(11415.21,5083.97)
PB0: J2.46 J6.4 U1.46 | length 1685.8
  Top Layer w6: U1.46@10922.86,4171.68 10922.86,3862.28 11014.66,3770.48 11362.76,3770.48 11449.96,3683.28 11449.96,3513.18 11529.16,3434.08 J2.46@11529.17,3367.08
  Bottom Layer w6: J2.46@11529.17,3367.08 11600.06,3437.98 11768.26,3437.98 11839.86,3509.58 J6.4@11839.86,3565.98
PB1: J2.47 U1.47 | length 1397.4
  Top Layer w6: U1.47@10942.56,4171.68 10942.56,3872.88 11029.96,3785.48 11385.76,3785.48 11472.46,3698.78 11472.46,3529.78 11578.26,3423.98 11578.26,3318.08 J2.47@11629.17,3267.08
PB2/BOOT1: J2.48 R14.2 U1.48 | length 3916.5
  Top Layer w6: v2@9123.26,4682.98 9188.46,4682.98 9245.96,4625.48 v2@9245.96,4602.58 ; v2(9248.21,3931.97) v2(10413.21,3931.97) ; U1.48@10962.26,4171.68 U1.48@10962.22,4171.68 v2(10962.21,3930.97) 10962.16,3883.98 11046.06,3800.08 11438.06,3800.08 11590.26,3647.88 11590.26,3493.88 11629.16,3454.98 J2.48@11629.17,3367.08
  Bottom Layer w6: R14.2@9072.76,4683.98 v2@9123.26,4682.98 ; v2(9245.95,4602.58) 9245.95,3934.23 v2(9248.21,3931.97) ; v2(10413.21,3931.97) 10414.21,3930.97 v2(10962.21,3930.97)
  other v2: 9123.21,4682.97
PB3: J1.61 J5.4 R23.2 U1.133 | length 4241.5
  Top Layer w6: J1.61@9829.16,5765.68 9878.26,5716.58 9878.26,5322.93 v2(9923.57,5277.61) 9923.86,5277.9 9923.86,5278.38 9952.26,5249.98 10865.2,5249.98 v2@10955.55,5159.63 ; v2@10955.56,5159.58 10962.26,5152.98 U1.133@10962.26,5008.28 ; v2(11103.68,5306.7) 11155.26,5358.28 11569.36,5358.28 11594.16,5383.18 11719.06,5383.18 11739.76,5403.78 J5.4@11739.8,5465.97
  Bottom Layer w6: R23.2@9167.76,4326.18 9167.66,4377.58 9223.86,4433.98 9223.86,4937.71 9363.38,5077.23 9817.5,5077.23 9878.26,5137.98 9878.26,5232.94 9922.93,5277.61 v2(9923.57,5277.61) ; v2@10955.55,5159.63 11102.62,5306.7 v2(11103.68,5306.7)
  other v2: 10955.55,5159.63
PB4: J1.62 J5.6 U1.134 | length 2465.4
  Top Layer w6: J1.62@9829.16,5665.68 9826.26,5662.68 9826.26,5305.98 9898.26,5233.98 10848.19,5233.98 v2(10906.68,5175.49) 10942.2,5139.97 ; 10942.16,5139.98 10942.16,5008.68 U1.134@10942.56,5008.28 ; v2(11070.58,5337.43) 11124.16,5390.98 11523.66,5390.98 11539.76,5407.08 J5.6@11539.8,5465.97
  Bottom Layer w6: v2(10906.68,5175.49) 10908.64,5175.49 v2(11070.58,5337.43)
PB5: J1.63 J5.5 U1.135 | length 2701.5
  Top Layer w6: J1.63@9729.16,5765.68 9778.26,5716.58 9778.26,5281.98 9842.26,5217.98 10831.46,5217.98 v2(10912.98,5136.49) 10922.86,5126.58 U1.135@10922.86,5008.28 ; v2(11102.89,5338.22) 11140.76,5376.08 11549.86,5376.08 J5.5@11639.8,5465.97
  Bottom Layer w6: v2(10912.98,5136.49) 10931.1,5154.61 10931.1,5166.04 11102.89,5337.82 v2(11102.89,5338.22)
PB6: J1.64 R60.2 U1.136 | length 1936.9
  Top Layer w6: J1.64@9729.16,5665.68 9729.16,5269.08 9796.26,5201.98 10813.16,5201.98 v2(10881.21,5133.97) 10903.16,5111.98 U1.136@10903.16,5008.31
  Bottom Layer w6: v2(10881.21,5133.97) 10881.16,5184.28 10926.16,5229.28 R60.2@10926.16,5312.88
PB7: J1.65 U1.137 | length 1882.2
  Top Layer w6: J1.65@9629.16,5765.68 9680.26,5714.58 9680.26,5271.88 9766.26,5185.98 10799.36,5185.98 10883.56,5101.68 U1.137@10883.56,5008.28
PB8: J1.67 J3.10 R58.1 U1.139 | length 5428.4
  Top Layer w6: J1.67@9529.16,5765.18 9578.26,5716.58 9578.26,5277.88 9704.26,5151.98 v2(10280.21,5151.97) 10779.26,5151.98 v2(10843.58,5087.62) 10843.56,5008.78 U1.139@10844.16,5008.18 ; v2@11184.27,5284.97 11264.36,5284.97 11276.85,5272.49 12285.45,5272.49 12285.45,5271.74 v2(12285.57,5271.61)
  Bottom Layer w6: J3.10@10279.86,5465.98 10279.86,5394.38 10280.16,5394.08 v2(10280.21,5151.97) ; v2(10843.58,5087.62) 10919.9,5087.62 11117.26,5284.98 v2@11184.26,5284.98 ; R58.1@12096.95,3722.38 12096.95,3807 12316.57,4026.61 12316.57,5240.61 v2(12285.57,5271.61)
  other v2: 11184.21,5284.97
PB9: J1.68 J3.9 R56.1 U1.140 | length 4975.9
  Top Layer w6: J1.68@9529.16,5665.18 9529.16,5252.98 9650.26,5131.98 v2(10379.81,5131.97) 10757.16,5131.98 10823.26,5065.98 10823.26,5009.38 U1.140@10824.46,5008.18 ; v2(11161.21,5264.97) 11261.21,5264.97 11267.21,5258.97 11905.21,5258.97 v2(11980.57,5183.61)
  Bottom Layer w6: v2@10379.86,5131.98 J3.9@10379.86,5465.98 ; v2(10823.21,5065.97) 10926.21,5065.97 11125.21,5264.97 v2(11161.21,5264.97) ; R56.1@11886.22,3723.08 11886.22,4439.26 11979.57,4532.61 11979.57,5020.61 12012.96,5054 12012.96,5151.23 v2(11980.57,5183.61)
PB10: J2.69 J5.7 U1.69 | length 4475.9
  Top Layer w6: U1.69@11375.66,4171.68 11375.66,4085.08 11416.86,4043.98 12078.36,4043.98 12283.36,3838.98 12283.36,3618.83 12373.6,3528.58 12600.66,3528.58 12678.26,3450.88 12678.26,3318.08 J2.69@12729.17,3267.08 ; v2(11529.2,5291.33) 12296.9,5291.28 v2(12313.57,5274.61)
  Bottom Layer w6: J5.7@11439.8,5465.97 11439.76,5407.48 11446.06,5401.28 11477.16,5401.28 11529.16,5349.28 v2@11529.16,5291.38 ; v2(12281.57,3839.61) 12338.57,3896.61 12338.57,5249.61 v2(12313.57,5274.61)
PB11: J2.70 J7.8 U1.70 | length 2237.5
  Top Layer w6: U1.70@11395.36,4171.68 11395.36,4094.98 11433.06,4057.28 12098.9,4057.28 ; 12098.73,4057.11 12303.57,3852.27 12303.57,3640.97 12395.86,3548.68 12627.76,3548.68 12729.16,3447.28 J2.70@12729.17,3367.08 ; 12103.96,4052.22 v1(12113.57,4042.61)
  Bottom Layer w6: v1(12113.57,4042.61) 12154.81,4083.85 J7.8@12154.81,4366.56
PB12: J1.1 J7.7 U1.73 | length 2455.2
  Top Layer w6: U1.73@11508.48,4245.5 11996.45,4245.5 12054.81,4303.85 J7.7@12054.81,4366.56 12072.51,4366.56 12122.57,4416.61 12197.57,4416.61 12224.01,4443.06 12224.01,4605.06 12561.07,4942.11 v2(12562.07,4942.11)
  Bottom Layer w6: v2(12562.07,4942.11) 12562.57,4942.61 12562.57,5318.52 12886.26,5642.35 12886.26,5708.58 J1.1@12829.16,5765.68
PB13: J1.2 J7.3 U1.74 | length 2268.4
  Top Layer w5.98: J7.3@12054.81,4566.56 12104.86,4616.61 12177.57,4616.61 12476.37,4915.41
  Top Layer w6: U1.74@11508.48,4265.19 11964.49,4265.19 v1(11973.74,4274.44) ; 12476.37,4915.41 12491.57,4930.61 12507.57,4930.61 v2(12525.57,4948.61)
  Bottom Layer w6: v1(11973.74,4274.44) 11973.74,4472.79 12054.81,4553.85 J7.3@12054.81,4566.56 ; v2(12525.57,4948.61) 12528.57,4948.61 12539.4,4959.44 12539.4,5336.44 12829.16,5626.2 J1.2@12829.16,5665.68
PB14: J1.3 J7.1 U1.75 | length 2368.3
  Top Layer w5.98: J7.1@12054.81,4666.56 12112.86,4724.61 12260.57,4724.61 12516.57,4980.61 v2(12516.57,4981.61)
  Top Layer w6: U1.75@11508.48,4284.87 11941.82,4284.87 v1(11949.57,4292.61)
  Bottom Layer w6: v1(11949.57,4292.61) 11949.57,4476.61 11995.57,4522.61 11995.57,4607.32 J7.1@12054.81,4666.56 ; v2(12516.57,4981.61) 12516.57,5356.61 12779.26,5619.3 12779.26,5715.58 J1.3@12729.16,5765.68
PB15: J1.4 J7.4 U1.76 | length 2133.7
  Top Layer w5.98: J7.4@12154.81,4566.56 12493.86,4905.61 v2(12494.57,4905.61)
  Top Layer w6: U1.76@11508.48,4304.56 11893.51,4304.56 12006.57,4417.61 12076.57,4417.61 12104.57,4445.61 12104.57,4516.32 J7.4@12154.81,4566.56
  Bottom Layer w6: v2(12494.57,4905.61) 12494.57,5377.47 12729.16,5612.25 J1.4@12729.16,5665.68
PC0: J2.26 R59.1 U1.26 | length 3291
  Top Layer w6: J2.26@10529.17,3367.08 10530.26,3368.08 10530.26,3411.93 10458.26,3483.93 10458.26,4359.3 10541.23,4442.28 U1.26@10671.86,4442.35 10675.56,4445.98 v2(11320.21,4445.97) ; v2(11328.21,4269.97) 11328.21,4267.98 11362.62,4233.56 11443.62,4233.56 11468.3,4208.88 11468.3,4159.58 11489.79,4138.09 12016.18,4138.09 v2(12016.97,4138.88)
  Bottom Layer w6: v2(11320.21,4445.97) 11328.21,4437.97 v2(11328.21,4269.97) ; v2(12016.97,4138.88) 12037.06,4118.79 R59.1@12037.06,3729.62
PC1: J2.27 R57.1 U1.27 | length 3300.3
  Top Layer w6: J2.27@10629.17,3267.08 10578.26,3318.08 10578.26,3391.93 10470.26,3499.93 10470.26,4347.3 10545.63,4422.68 U1.27@10671.86,4422.67 10672.26,4422.98 v2(11307.21,4422.97) ; v2(11307.21,4246.97) 11307.16,4244.03 11329.62,4221.56 11438.62,4221.56 11456.3,4203.88 11456.3,4148.34 11480.41,4124.23 11910.45,4124.23 11916.69,4118 v2(11938.17,4118)
  Bottom Layer w6: v2(11307.21,4246.97) v2(11307.21,4422.97) ; v2(11938.17,4118) 11938.22,3729.42 R57.1@11940.16,3727.48
PC2: J2.28 U1.28 | length 1245.1
  Top Layer w6: J2.28@10629.1,3367.08 10485.57,3510.61 10485.57,4340.61 10547.93,4402.98 U1.28@10671.86,4402.98
PC3: J2.29 U1.29 | length 1390.1
  Top Layer w6: U1.29@10671.86,4383.3 10545.2,4383.28 10497.57,4335.64 10497.57,3526.61 10593.57,3430.61 10647.66,3430.61 10682.26,3395.89 10682.26,3314.08 J2.29@10729.17,3267.08
PC4: J2.44 U1.44 | length 1227.3
  Top Layer w6: U1.44@10883.56,4171.68 10883.56,3834.98 10979.56,3738.98 11315.26,3738.98 11406.26,3647.98 11406.26,3478.18 11429.36,3454.98 J2.44@11429.17,3367.08
PC5: J2.45 U1.45 | length 1362.3
  Top Layer w6: U1.45@10903.16,4171.68 10903.16,3850.38 10998.06,3755.48 11336.76,3755.48 11428.26,3663.98 11428.26,3499.98 11480.26,3447.98 11480.26,3316.08 J2.45@11529.17,3267.08
PC6: J1.24 U1.96 | length 1257.2
  Top Layer w6: U1.96@11508.56,4698.28 11573.58,4698.28 v2(11573.72,4698.36)
  Bottom Layer w6: v2(11573.72,4698.36) 11632.04,4698.37 11743.96,4810.29 11743.96,5275.68 11881.46,5413.18 11881.46,5513.38 J1.24@11729.16,5665.68
PC7: J1.25 J3.2 U1.97 | length 2167
  Top Layer w6: J3.2@11079.86,5465.98 11079.86,5539.58 11178.26,5637.98 11178.26,5797.98 11208.26,5827.98 11566.86,5827.98 J1.25@11629.16,5765.68 ; U1.97@11508.56,4717.88 11624.3,4717.88 v2(11624.54,4718.06)
  Bottom Layer w6: v2(11624.54,4718.06) 11729.76,4823.34 11729.76,5341.48 11797.56,5409.18 11797.56,5516.78 11680.26,5633.98 11680.26,5714.58 J1.25@11629.16,5765.68
PC8: J1.26 U1.98 | length 1168.5
  Top Layer w6: U1.98@11508.56,4737.58 11592.77,4737.58 v2(11593.42,4736.97)
  Bottom Layer w6: v2(11593.42,4736.97) 11614.7,4736.98 11715.16,4837.44 11715.16,5348.78 11782.96,5416.58 11782.96,5505.18 11629.16,5658.98 J1.26@11629.16,5665.68
PC9: J1.27 U1.99 | length 1255
  Top Layer w6: U1.99@11508.56,4757.28 11566.78,4757.28 v2(11567.02,4757.46)
  Bottom Layer w6: J1.27@11529.16,5765.68 11580.26,5714.58 11580.26,5586.18 11594.96,5571.48 11655.66,5571.48 11699.76,5527.38 11699.76,4844.1 11613.13,4757.47 v2(11567.02,4757.46)
PC10: J1.39 U1.111 | length 1052.5
  Top Layer w6: v2(11395.21,5109.97) 11395.16,5008.38 U1.111@11395.36,5008.28
  Bottom Layer w6: J1.39@10929.16,5765.68 10978.26,5716.58 10978.26,5635.98 11006.26,5607.98 11058.26,5607.98 11095.26,5570.98 11217.26,5570.98 11254.26,5533.98 11254.26,5418.88 11395.16,5278.08 v2(11395.21,5109.97)
PC11: J1.40 U1.112 | length 963.4
  Top Layer w6: U1.112@11375.66,5008.28 11376.16,5008.88 v2(11376.21,5062.97)
  Bottom Layer w6: J1.40@10929.16,5665.68 10929.16,5620.98 10958.26,5591.98 11048.16,5591.98 11086.16,5553.98 11202.16,5553.98 11238.16,5517.98 11238.16,5412.88 11376.16,5274.98 v2(11376.21,5062.97)
PC12: J1.41 U1.113 | length 1108.7
  Top Layer w6: U1.113@11355.96,5008.28 11356.16,5008.58 v2(11356.21,5086.97)
  Bottom Layer w6: J1.41@10829.16,5765.68 10880.26,5714.58 10880.26,5609.88 10914.26,5575.98 11037.26,5575.98 11074.26,5538.98 11103.26,5538.98 11138.26,5503.98 11138.26,5415.58 11170.66,5383.18 11245.56,5383.18 11356.16,5272.48 v2(11356.21,5086.97)
PC13: J2.7 R20.2 U1.7 | length 3158.1
  Top Layer w6: R20.2@9326.5,3602.96 9518.26,3602.98 9579.26,3541.98 9579.26,3317.08 J2.7@9629.17,3267.08 ; v2(9766.21,4797.97) 9834.76,4866.58 10545.36,4866.58 10595.56,4816.38 U1.7@10671.86,4816.37
  Bottom Layer w6: J2.7@9629.16,3267.18 9629.16,3270.98 9578.26,3322.18 9578.26,3391.88 9644.21,3457.83 9644.21,4675.97 v2(9766.21,4797.97)
PC14/LEXT_IN: R5.2 R7.2 U1.8 | length 223.5
  Top Layer w5.98: R5.2@10499.47,4804.66 10534.85,4804.66 v2(10543.56,4795.95)
  Top Layer w6: v2(10543.56,4795.95) 10544.29,4796.68 U1.8@10671.86,4796.68
  Bottom Layer w5.98: R7.2@10496.91,4794.69 10542.3,4794.69 v2(10543.56,4795.95)
PC14_E: J2.8 R7.1 | length 2163.4
  Bottom Layer w5.98: 10357.86,4670.38 10384.92,4670.38 10409.1,4694.55 10409.1,4778.06 10425.72,4794.69 R7.1@10452.51,4794.69
  Bottom Layer w6: J2.8@9629.16,3367.18 9662.26,3400.28 9662.26,4594.98 9737.66,4670.38 10357.86,4670.38
PC15/LEXT_OUT: R6.2 R8.2 U1.9 | length 239.5
  Top Layer w5.98: R6.2@10499.47,4747.93 10523.84,4747.93 10529.95,4754.04 10542.65,4754.04 v2(10545.36,4756.75)
  Top Layer w6: v2(10545.36,4756.75) 10565.59,4776.98 U1.9@10671.86,4777
  Bottom Layer w5.98: R8.2@10496.91,4740.69 10529.3,4740.69 v2(10545.36,4756.75)
PC15_E: J2.9 R8.1 | length 2212.5
  Bottom Layer w5.98: 10385.76,4655.38 10426.35,4655.38 10452.51,4681.54 R8.1@10452.51,4740.69
  Bottom Layer w6: J2.9@9729.17,3267.08 9680.56,3315.68 9680.56,4590.78 9745.16,4655.38 10385.76,4655.38
PD0: J1.42 U1.114 | length 1025.3
  Top Layer w6: v2(11336.13,5141.22) 11336.08,5008.45 U1.114@11336.26,5008.28
  Bottom Layer w6: J1.42@10829.16,5665.68 10829.16,5596.98 10864.26,5561.98 11022.26,5561.98 11062.16,5521.98 11094.26,5521.98 11122.26,5493.98 11122.26,5404.58 11160.26,5366.58 11239.56,5366.58 11336.08,5270.05 v2(11336.13,5141.22)
PD1: J1.43 U1.115 | length 1178.1
  Top Layer w6: v2(11316.43,5164.07) 11316.38,5008.45 U1.115@11316.56,5008.28
  Bottom Layer w6: J1.43@10729.16,5765.68 10778.26,5716.58 10778.26,5585.88 10818.26,5545.98 11006.26,5545.98 11036.26,5515.98 11036.26,5433.88 11063.76,5406.38 11095.86,5406.38 11153.26,5348.98 11235.96,5348.98 11316.38,5268.55 v2(11316.43,5164.07)
PD2: J1.44 U1.116 | length 1087.8
  Top Layer w6: U1.116@11296.86,5008.31 11297.16,5008.58 v2(11297.21,5083.97)
  Bottom Layer w6: J1.44@10729.16,5665.68 10729.16,5576.98 10778.26,5527.98 10996.26,5527.98 11022.26,5501.98 11022.26,5424.98 11056.76,5390.48 11086.76,5390.48 11144.26,5332.98 11229.06,5332.98 11297.16,5264.88 v2(11297.21,5083.97)
PD3: J1.45 U1.117 | length 1188.7
  Top Layer w6: J1.45@10629.18,5765.65 10678.21,5716.62 10678.21,5641.97 ; 10678.26,5641.98 10678.26,5635.88 10714.16,5599.98 10992.16,5599.98 11038.26,5553.98 11038.26,5336.98 11277.26,5097.88 U1.117@11277.26,5008.28
PD4: J1.46 U1.118 | length 1087.6
  Top Layer w6: J1.46@10629.16,5665.68 10629.16,5642.98 10690.16,5581.98 10980.26,5581.98 11022.26,5539.98 11022.26,5333.98 11257.56,5098.58 U1.118@11257.56,5008.28
PD5: J1.47 U1.119 | length 1182.1
  Top Layer w6: J1.47@10529.16,5765.68 10580.26,5714.58 10580.26,5637.98 10652.26,5565.98 10876.26,5565.98 10928.26,5513.98 10928.26,5404.98 11237.86,5095.28 U1.119@11237.86,5008.28
PD6: J1.50 U1.122 | length 1167.3
  Top Layer w6: J1.50@10429.16,5665.68 10488.86,5605.98 10584.26,5605.98 10644.26,5545.98 10792.26,5545.98 10828.26,5509.88 10828.26,5427.98 10864.26,5391.98 10920.26,5391.98 11178.76,5133.38 U1.122@11178.76,5008.28 ; J1.50@10429.18,5665.65 J1.50@10446.21,5648.62
PD7: J1.51 U1.123 | length 1298.3
  Top Layer w6: J1.51@10329.16,5765.68 10380.26,5714.58 10380.26,5640.58 10436.86,5583.98 10580.26,5583.98 10634.26,5529.98 10694.26,5529.98 10730.26,5493.98 10730.26,5427.88 10782.26,5375.98 10915.26,5375.98 11159.16,5131.98 U1.123@11159.16,5008.28
PD8: J1.5 U1.77 | length 2320.6
  Top Layer w6: U1.77@11508.56,4324.18 v2@11708.26,4324.18 ; v2(11989.39,5101.03) 12012.24,5123.88 12409.72,5123.88 v2(12431.36,5145.53)
  Bottom Layer w6: v2@11708.26,4324.18 11747.46,4324.18 11962.99,4539.71 11962.99,5074.57 v2(11989.39,5101.03) ; v2(12431.36,5145.53) 12474.57,5188.73 12474.57,5402.61 12680.07,5608.11 12680.07,5714.76 J1.5@12629.18,5765.65
  other v2: 11708.21,4324.22
PD9: J1.6 U1.78 | length 2154.2
  Top Layer w6: U1.78@11508.56,4343.88 v2@11680.26,4343.88 ; v2(11961.41,5104.18) 11997.27,5140.03 12394.36,5140.03 v2(12436.91,5182.59)
  Bottom Layer w6: v2@11680.26,4343.88 11740.16,4343.88 11948.8,4552.53 11948.8,5091.57 v2(11961.41,5104.18) ; v2(12436.91,5182.59) 12452.57,5198.25 12452.57,5420.61 12629.18,5597.22 J1.6@12629.18,5665.65
  other v2: 11680.21,4343.91
PD10: J1.7 U1.79 | length 2229
  Top Layer w6: U1.79@11508.56,4363.58 11508.86,4363.98 v2@11710.26,4363.98 ; v2(11962.2,5134.12) 11984.33,5156.26 12381.1,5156.26 v2(12399.88,5175.04)
  Bottom Layer w6: v2@11710.26,4363.98 11731.26,4363.98 11935.41,4568.13 11935.41,5107.3 v2(11962.2,5134.12) ; v2(12399.88,5175.04) 12431.57,5206.73 12431.57,5438.61 12579.2,5586.25 12579.2,5715.62 J1.7@12529.18,5765.65
  other v2: 11710.21,4363.97
PD11: J1.8 U1.80 | length 2001.5
  Top Layer w6: U1.80@11508.56,4383.28 11509.26,4383.98 v2@11678.26,4383.98
  Bottom Layer w6: v2@11678.26,4383.98 11725.26,4383.98 11920.26,4578.98 11920.26,5155.98 12042.26,5277.98 12124.26,5277.98 12214.26,5367.98 12214.26,5497.98 12286.26,5569.98 12494.16,5569.98 12529.16,5604.98 J1.8@12529.16,5665.68
  other v2: 11678.21,4383.97
PD12: J1.9 U1.81 | length 2039.9
  Top Layer w6: U1.81@11508.56,4402.98 v2@11710.26,4402.98
  Bottom Layer w6: v2@11710.26,4402.98 11906.26,4598.98 11906.26,5161.98 12034.26,5289.98 12114.26,5289.98 12198.26,5373.98 12198.26,5503.98 12282.26,5587.98 12436.26,5587.98 12478.26,5629.98 12478.26,5716.58 J1.9@12429.16,5765.68
  other v2: 11710.21,4402.95
PD13: J1.10 LED2.2 U1.82 | length 4498.8
  Top Layer w6: LED2.2@9472.01,4735.2 9512.66,4775.88 v2(9512.71,4776.37) ; v2(10786.63,4502.66) 11343.47,4502.66 11423.45,4422.68 11508.56,4422.68 11509.16,4421.98 v2(11680.21,4421.97)
  Bottom Layer w6: v2(9512.71,4776.37) 9512.66,4937.58 9556.73,4981.58 10642.76,4981.58 10786.63,4837.71 v2(10786.63,4502.66) ; v2(11680.21,4421.97) 11701.26,4421.98 11892.26,4612.98 11892.26,5167.98 12028.26,5303.98 12106.86,5303.98 12182.26,5379.38 12182.26,5509.98 12276.26,5603.98 12367.46,5603.98 J1.10@12429.16,5665.68
PD14: J1.13 LED3.2 U1.85 | length 4325.1
  Top Layer w6: LED3.2@9472.06,4810.18 9472.16,4810.28 v2(9535.73,4810.28) ; v2(10767.03,4521.5) 11418.64,4521.5 11458.46,4481.68 11508.56,4481.68 11508.56,4484.78 11679.06,4484.78 v2@11694.26,4499.98
  Bottom Layer w6: v2(9535.73,4810.28) 9535.73,4919.16 9586.16,4969.58 10637.79,4969.58 10767.26,4840.11 10767.26,4521.73 v2(10767.03,4521.5) ; v2@11694.26,4499.98 11878.26,4683.98 11878.26,5173.98 12022.26,5317.98 12099.16,5317.98 12166.26,5385.08 12166.26,5524.48 12280.26,5638.58 12280.26,5714.58 J1.13@12229.16,5765.68
  other v2: 11694.21,4499.97
PD15: J1.14 LED4.2 U1.86 | length 4075.4
  Top Layer w6: LED4.2@9472.06,4886.48 v2(9573.38,4887.09) ; v2(10748.42,4540.34) 11429.39,4540.34 11468.36,4501.38 11508.56,4501.38 11667.66,4501.38 v2(11710.21,4543.97) ; J1.14@12229.16,5640.68 J1.14@12229.16,5665.68
  Bottom Layer w6: v2(9573.38,4887.09) 9573.36,4916.98 9613.96,4957.58 10632.82,4957.58 10748.84,4841.56 10748.84,4540.77 v2(10748.42,4540.34) ; v2(11710.21,4543.97) 11862.26,4695.98 11862.26,5179.98 12016.26,5333.98 12093.46,5333.98 12150.76,5391.28 12150.76,5532.28 12229.16,5610.68 J1.14@12229.16,5665.68
PE0: J1.69 U1.141 | length 1994.3
  Top Layer w6: J1.69@9429.16,5765.18 9480.26,5714.58 9480.26,5593.88 9498.96,5575.18 9498.96,5221.28 9607.11,5113.13 10746.41,5113.13 10804.76,5054.78 U1.141@10804.76,5008.18
PE1: J1.70 U1.142 | length 1905
  Top Layer w6: J1.70@9429.16,5665.18 9429.16,5582.98 9470.26,5541.88 9470.26,5195.88 9570.67,5095.57 10742.37,5095.57 10785.06,5052.88 U1.142@10785.06,5008.18
PE2: J2.1 U1.1 | length 2861.3
  Top Layer w6: v2(9652.16,4853.98) 9748.26,4950.08 10618.26,4950.08 10633.96,4934.48 U1.1@10671.86,4934.48
  Bottom Layer w6: J2.1@9329.17,3267.08 9307.16,3267.08 9262.26,3311.98 9262.26,3383.98 9545.96,3667.68 9545.96,4561.18 9538.26,4568.78 9538.26,4740.08 v2(9652.16,4853.98)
